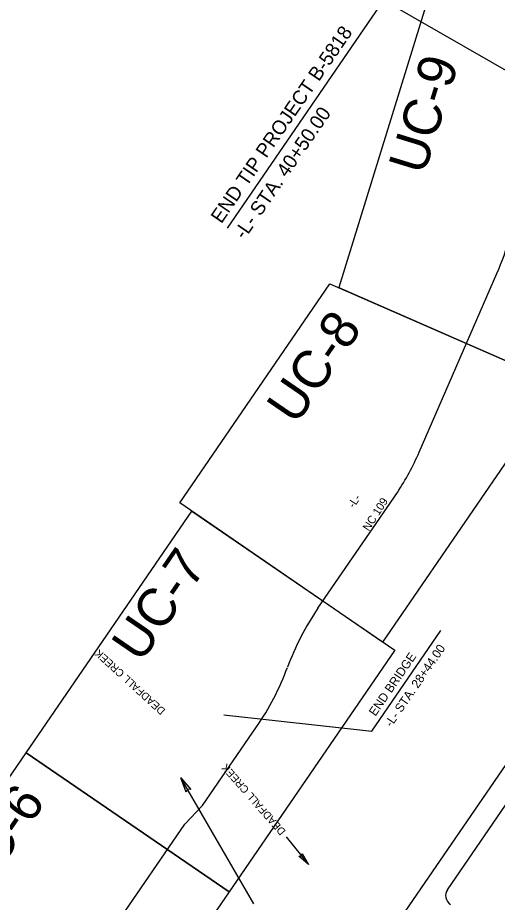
# Model space of a CAD drawing. Extents: x 1638787 to 1643250, y 391480 to 396306.
# Drawn here: x 1641236 to 1642055, y 393769 to 395279 of the extents above; entities that cross this region are included whole.
import ezdxf

# ---------------------------------------------------------------- set-up
doc = ezdxf.new("R2010")
doc.units = 0
for name, color, linetype in [('Old_Level_1', 7, 'Continuous'), ('Prop 8 In Water Line (St)', 7, 'Continuous'), ('Prop Terminator CELL', 7, 'Continuous'), ('Sheet Plan Layout CELL', 7, 'Continuous'), ('UC Title Plan Sheet 34 CELL', 7, 'Continuous')]:
    doc.layers.add(name, color=color, linetype=linetype)

msp = doc.modelspace()

# ---------------------------------------------------------------- linework, layer by layer
at = {"layer": 'Old_Level_1'}
for p, q in [((1641860.2, 395308.7), (1641593.3, 394919.4)), ((1641860.2, 395308.7), (1642122.8, 395158.2)), ((1641840.6, 394061.1), (1641958.4, 394232.9)), ((1641587.6, 394088.7), (1641840.6, 394061.1)), ((1641638.6, 393766.5), (1641514, 393981.5)), ((1641693.8, 393880.7), (1641732.3, 393833.3))]:
    msp.add_line(p, q, dxfattribs=at)
at = {"layer": 'Prop 8 In Water Line (St)'}
for p, q in [((1641921.3, 394537.3), (1642054, 394842.1)), ((1641748.4, 394270.7), (1641884.1, 394468.6)), ((1641551.1, 393934.1), (1641643.6, 394068.4)), ((1641521.3, 393902.5), (1641551.1, 393934.1)), ((1641404.6, 393733.1), (1641521.3, 393902.5))]:
    msp.add_line(p, q, dxfattribs=at)
for centre, start, end in [((1641632.2, 395025.7), 336.4656, 344.8307), ((1641499.5, 394721), 326.7156, 336.4656), ((1642127.8, 394010.6), 145.5597, 159.7274), ((1641264.8, 394329.3), 325.4432, 339.7274)]:
    msp.add_arc(centre, 460, start, end, dxfattribs=at)
at = {"layer": 'Prop Terminator CELL'}
for points in [[(1641523.2, 393956.8), (1641514, 393981.5), (1641531.1, 393961.2), (1641525.4, 393961.8)], [(1641721.6, 393852.4), (1641732.3, 393833.3), (1641715.6, 393847.7), (1641720.4, 393848)]]:
    msp.add_lwpolyline(points, close=True, dxfattribs=at)
at = {"layer": 'Sheet Plan Layout CELL'}
for points in [[(1642171.6, 394648.6), (1642348, 395222.1), (1641946.6, 395345.6), (1641784.3, 394818.2)], [(1641858.7, 394213.2), (1641512.3, 394450.7), (1641768.9, 394824.9), (1642160.6, 394653.5)], [(1641250.2, 394024.1), (1641533, 394436.5), (1641879.4, 394199), (1641596.6, 393786.6)], [(1640975.6, 393623.7), (1641250.2, 394024.1), (1641596.6, 393786.6), (1641307.7, 393365.2)]]:
    msp.add_lwpolyline(points, close=True, dxfattribs=at)
at = {"layer": 'UC Title Plan Sheet 34 CELL'}
for p, q in [((1640853.8, 392231.2), (1642781.2, 395041.9)), ((1641969.4, 393790.4), (1642294.2, 394263.7))]:
    msp.add_line(p, q, dxfattribs=at)
msp.add_ellipse((1641985, 393779.7), major_axis=(-15.6, 10.7), ratio=0.941469, start_param=6.283006, end_param=7.853383, dxfattribs=at)

# ---------------------------------------------------------------- texts
at = {"layer": 'Old_Level_1'}
for s, height, rotation, p in [('END TIP PROJECT B-5818', 24, 55.5597, (1641583.4, 394926.2)), ('UC-9', 64.8, 72.9038, (1641929.8, 395008.7)), ('-L- STA. 40+50.00', 24, 55.5597, (1641622.9, 394899)), ('UC-8', 64.8, 55.5597, (1641710.7, 394581.9)), ('-L-', 13.71, 57.3772, (1641809.9, 394440.9)), ('NC 109', 13.71, 57.3772, (1641835.2, 394401.5)), ('UC-7', 64.8, 55.5597, (1641445.9, 394175.7)), ('-L- STA. 28+44.00', 15, 55.5597, (1641873.7, 394066.9)), ('DEADFALL CREEK', 13, 137.5766, (1641488.8, 394097.3)), ('END BRIDGE', 15, 55.5597, (1641846.5, 394085.6)), ('DEADFALL CREEK', 13, 131.2487, (1641694.2, 393890.4)), ('UC-6', 64.8, 55.5597, (1641170, 393773.4))]:
    msp.add_text(s, height=height, rotation=rotation, dxfattribs=at).set_placement(p)

doc.saveas('drawing.dxf')
